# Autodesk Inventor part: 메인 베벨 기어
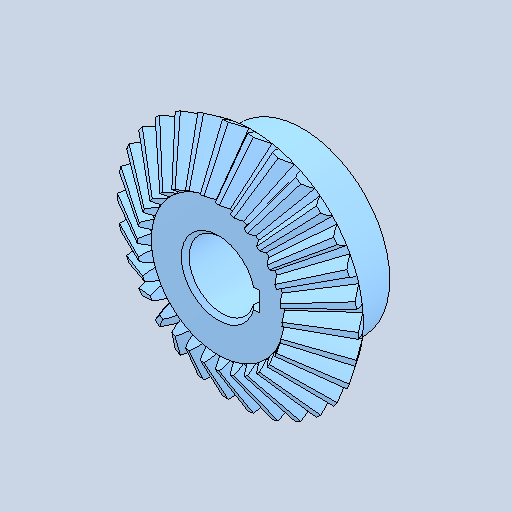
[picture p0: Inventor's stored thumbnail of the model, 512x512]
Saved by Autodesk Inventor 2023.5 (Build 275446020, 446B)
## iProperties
Created: 2026-07
Part Number: 메인 베벨 기어
Material: 강철, 합금
Document SubType Name: Modeling
Designer: mirae
Density: 7.73 g/cm^3
Appearance: 기본값
Author: jhkim
Revision Number: 1
Sending System: Autodesk Inventor 2027
Preprocessor: ST-DEVELOPER v20.1
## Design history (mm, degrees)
node "메인 베벨기어1"
node "솔리드1"
body "Solid1"
